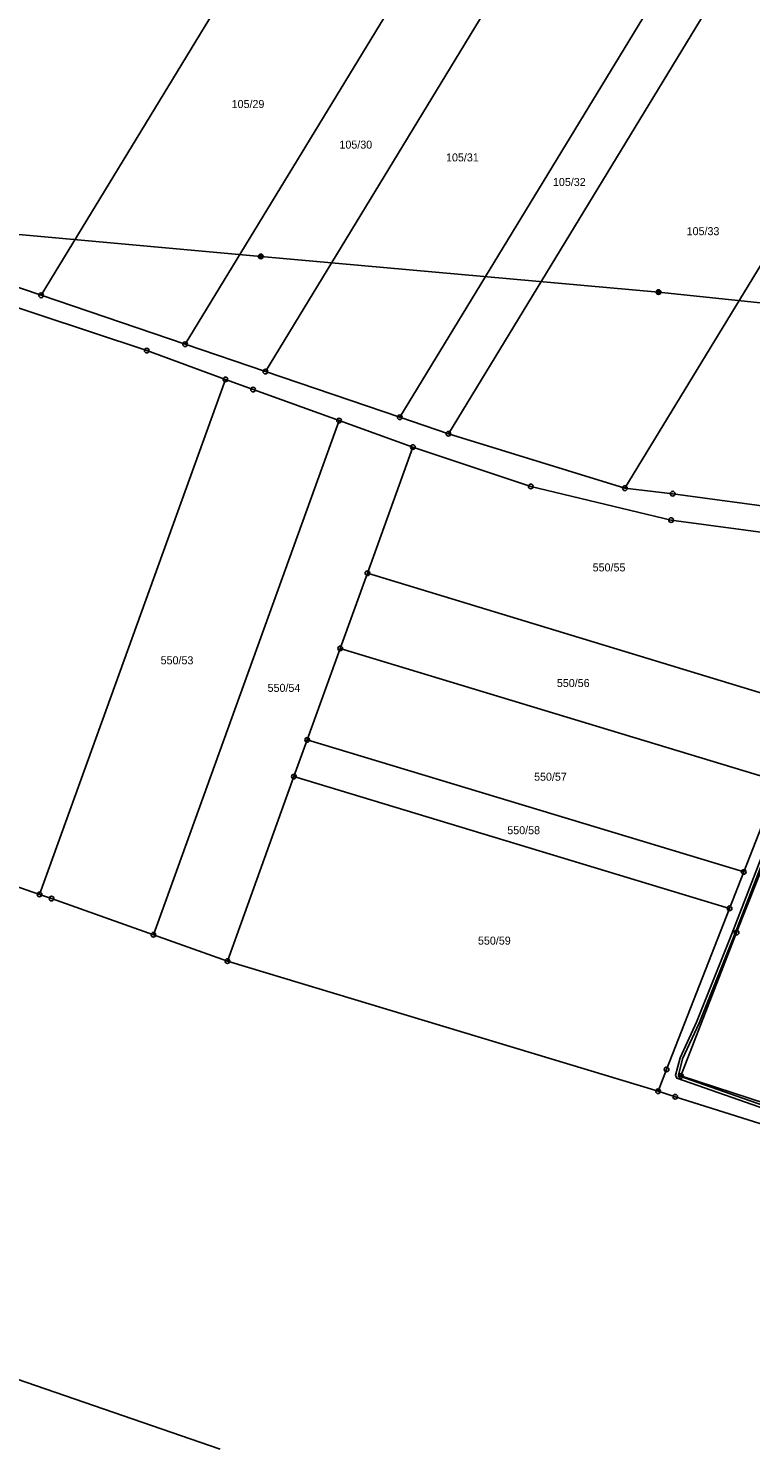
# Model space of a CAD drawing. Extents: x -758582 to -751794, y -998770 to -994350.
# Drawn here: x -754914.8 to -754761.3, y -997060.6 to -996760.3 of the extents above; entities that cross this region are included whole.
import ezdxf

# ---------------------------------------------------------------- set-up
doc = ezdxf.new("R2010")
doc.units = 0
for name, color, linetype in [('Hranice parcel', 7, 'Continuous'), ('Parcelní čísla', 7, 'Continuous'), ('Poz předměty', 7, 'Continuous'), ('Věcná břemena k části', 7, 'Continuous'), ('Značky bodu BP', 7, 'Continuous')]:
    doc.layers.add(name, color=color, linetype=linetype)

msp = doc.modelspace()

# ---------------------------------------------------------------- linework, layer by layer
at = {"layer": 'Hranice parcel'}
for p, q in [((-754912.07, -996817), (-754851.18, -996716.96)), ((-754881.47, -996827.39), (-754820.01, -996726.44)), ((-754864.4, -996833.2), (-754802.63, -996731.72)), ((-754835.86, -996842.9), (-754773.56, -996740.55)), ((-754825.52, -996846.41), (-754763.03, -996743.75)), ((-754725.45, -996755.18), (-754788.01, -996857.97)), ((-754881.47, -996827.39), (-754912.07, -996817)), ((-754864.4, -996833.2), (-754881.47, -996827.39)), ((-754912.41, -996944.29), (-754872.91, -996834.87)), ((-754835.86, -996842.9), (-754864.4, -996833.2)), ((-754888.21, -996952.86), (-754848.76, -996843.6)), ((-754848.76, -996843.6), (-754833.07, -996849.25)), ((-754825.52, -996846.41), (-754835.86, -996842.9)), ((-754788.01, -996857.97), (-754825.52, -996846.41)), ((-754842.74, -996876.04), (-754833.07, -996849.25)), ((-754848.52, -996892.03), (-754842.74, -996876.04)), ((-754842.74, -996876.04), (-754749.12, -996904.51)), ((-754855.53, -996911.46), (-754848.52, -996892.03)), ((-754848.52, -996892.03), (-754755.25, -996920.32)), ((-754858.34, -996919.26), (-754855.53, -996911.46)), ((-754855.53, -996911.46), (-754762.75, -996939.51)), ((-754872.49, -996958.44), (-754858.34, -996919.26)), ((-754858.34, -996919.26), (-754765.77, -996947.24)), ((-754762.75, -996939.51), (-754755.25, -996920.32)), ((-754765.77, -996947.24), (-754762.75, -996939.51)), ((-754872.49, -996958.44), (-754888.21, -996952.86)), ((-754780.97, -996986.1), (-754872.49, -996958.44))]:
    msp.add_line(p, q, dxfattribs=at)
for points in [[(-754912.07, -996817), (-754950.28, -996804.01), (-755004.32, -996785.02)], [(-754936.27, -996813.27), (-754889.63, -996828.75), (-754872.91, -996834.87)], [(-754788.01, -996857.97), (-754777.86, -996859.14), (-754753.65, -996862.43), (-754736.1, -996862.72), (-754724.6, -996858.08), (-754709.52, -996842.19), (-754700.41, -996830.56), (-754697.46, -996826.81)], [(-754872.91, -996834.87), (-754867.04, -996837.02), (-754848.76, -996843.6)], [(-754833.07, -996849.25), (-754808.02, -996857.61), (-754778.19, -996864.75), (-754754.41, -996867.99), (-754735.78, -996867.55)], [(-754912.41, -996944.29), (-754934.11, -996936.73), (-754975.39, -996921.61)], [(-754751.25, -996919.6), (-754764.28, -996952.39), (-754776.09, -996982.86), (-754757.9, -996988.78)], [(-754888.21, -996952.86), (-754909.86, -996945.18), (-754912.41, -996944.29)], [(-754780.97, -996986.1), (-754779.16, -996981.47), (-754765.77, -996947.24)], [(-754667.26, -997021.62), (-754673, -997019.84), (-754704.67, -997010.01), (-754726.66, -997003.45), (-754741.11, -996998.69), (-754777.3, -996987.26), (-754780.97, -996986.1)]]:
    msp.add_lwpolyline(points, dxfattribs=at)
at = {"layer": 'Poz předměty'}
for p, q in [((-754946.71, -996801.38), (-754865.39, -996808.72)), ((-754865.39, -996808.72), (-754780.86, -996816.32)), ((-754780.86, -996816.32), (-754700.95, -996824.72)), ((-754932.31, -997042.03), (-754874.02, -997062.14))]:
    msp.add_line(p, q, dxfattribs=at)
for centre, radius in [((-754865.39, -996808.72), 0.5), ((-754865.39, -996808.72), 0.4), ((-754865.39, -996808.72), 0.3), ((-754865.39, -996808.72), 0.2), ((-754865.39, -996808.72), 0.1), ((-754780.86, -996816.32), 0.5), ((-754780.86, -996816.32), 0.4), ((-754780.86, -996816.32), 0.3), ((-754780.86, -996816.32), 0.2), ((-754780.86, -996816.32), 0.1)]:
    msp.add_circle(centre, radius, dxfattribs=at)
at = {"layer": 'Věcná břemena k části'}
for points in [[(-754750.97, -996915.68), (-754765.29, -996952.68), (-754772.8, -996971.4), (-754776.3, -996979.03), (-754777.23, -996982.69), (-754776.99, -996983.31), (-754747.82, -996993.51)], [(-754747.64, -996992.95), (-754776.53, -996982.83), (-754776.61, -996982.65), (-754775.74, -996979.23), (-754772.24, -996971.64), (-754764.73, -996952.9), (-754750.41, -996915.88)]]:
    msp.add_lwpolyline(points, dxfattribs=at)
at = {"layer": 'Značky bodu BP'}
for centre, radius in [((-754912.07, -996817), 0.5), ((-754912.07, -996817), 0.0303), ((-754889.63, -996828.75), 0.5), ((-754889.63, -996828.75), 0.0303), ((-754881.47, -996827.39), 0.5), ((-754881.47, -996827.39), 0.0303), ((-754872.91, -996834.87), 0.5), ((-754872.91, -996834.87), 0.0303), ((-754864.4, -996833.2), 0.5), ((-754864.4, -996833.2), 0.0303), ((-754867.04, -996837.02), 0.5), ((-754867.04, -996837.02), 0.0303), ((-754848.76, -996843.6), 0.5), ((-754848.76, -996843.6), 0.0303), ((-754835.86, -996842.9), 0.5), ((-754835.86, -996842.9), 0.0303), ((-754825.52, -996846.41), 0.5), ((-754825.52, -996846.41), 0.0303), ((-754833.07, -996849.25), 0.5), ((-754833.07, -996849.25), 0.0303), ((-754808.02, -996857.61), 0.5), ((-754808.02, -996857.61), 0.0303), ((-754788.01, -996857.97), 0.5), ((-754788.01, -996857.97), 0.0303), ((-754777.86, -996859.14), 0.5), ((-754777.86, -996859.14), 0.0303), ((-754778.19, -996864.75), 0.5), ((-754778.19, -996864.75), 0.0303), ((-754842.74, -996876.04), 0.5), ((-754842.74, -996876.04), 0.0303), ((-754848.52, -996892.03), 0.5), ((-754848.52, -996892.03), 0.0303), ((-754855.53, -996911.46), 0.5), ((-754855.53, -996911.46), 0.0303), ((-754858.34, -996919.26), 0.5), ((-754858.34, -996919.26), 0.0303), ((-754762.75, -996939.51), 0.5), ((-754762.75, -996939.51), 0.0303), ((-754912.41, -996944.29), 0.5), ((-754912.41, -996944.29), 0.0303), ((-754909.86, -996945.18), 0.5), ((-754909.86, -996945.18), 0.0303), ((-754765.77, -996947.24), 0.5), ((-754765.77, -996947.24), 0.0303), ((-754764.28, -996952.39), 0.5), ((-754888.21, -996952.86), 0.5), ((-754888.21, -996952.86), 0.0303), ((-754764.28, -996952.39), 0.0303), ((-754872.49, -996958.44), 0.5), ((-754872.49, -996958.44), 0.0303), ((-754779.16, -996981.47), 0.5), ((-754779.16, -996981.47), 0.0303), ((-754776.09, -996982.86), 0.5), ((-754776.09, -996982.86), 0.0303), ((-754780.97, -996986.1), 0.5), ((-754780.97, -996986.1), 0.0303), ((-754777.3, -996987.26), 0.5), ((-754777.3, -996987.26), 0.0303)]:
    msp.add_circle(centre, radius, dxfattribs=at)

# ---------------------------------------------------------------- texts
at = {"layer": 'Parcelní čísla'}
for s, p in [('105/29', (-754871.58, -996777.21)), ('105/30', (-754848.67, -996785.83)), ('105/31', (-754826.02, -996788.55)), ('105/32', (-754803.3, -996793.77)), ('105/33', (-754774.89, -996804.22)), ('550/55', (-754794.86, -996875.66)), ('550/53', (-754886.67, -996895.39)), ('550/54', (-754863.94, -996901.25)), ('550/56', (-754802.47, -996900.22)), ('550/57', (-754807.31, -996920.13)), ('550/58', (-754813, -996931.49)), ('550/59', (-754819.23, -996954.95))]:
    msp.add_text(s, height=1.7, dxfattribs=at).set_placement(p)

doc.saveas('drawing.dxf')
